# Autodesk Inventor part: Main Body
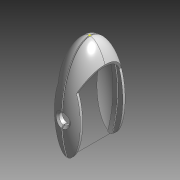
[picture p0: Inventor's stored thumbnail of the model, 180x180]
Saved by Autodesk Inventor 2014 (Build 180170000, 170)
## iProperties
Created: 2013-09
Part Number: Main Body
Material: Generic
Document SubType Name: Modeling
Designer: Joey Mason
Appearance: Reflective - White
Mass: 1001.7 g
Surface Area: 2819.14 cm^2
Volume: 1001.7 cm^3
Density: 1 g/cm^3
Author: Joey Mason
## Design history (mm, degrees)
sketch "Sketch1"
  geometry: L1 (-1045.953, 551.745)-(799.079, 551.745); L2 (799.079, 551.745)-(799.079, -678.891); L3 (799.079, -678.891)-(-1045.953, -678.891); L4 (-1045.953, -678.891)-(-1045.953, 551.745); 4 further points; 1 other entity
  constraints: 1 vertical, 6 other
  node "Image1"
sketch "Sketch6"
  geometry: 5 further points; 1 other entity
  constraints: 1 coincident, 4 other
sketch "Sketch7"
  geometry: 4 further points; 1 other entity
  constraints: 1 coincident, 4 other
sketch "Sketch8"
  geometry: 4 further points; 1 other entity
  constraints: 4 other
sketch "Sketch9"
  geometry: 5 further points; 1 other entity
  constraints: 1 coincident, 2 other
workpoint "Work Point5"
loft "Loft2" dims "d70" = 0, "d71" = 90 deg, "d72" = 0, "d73" = 90 deg, "d74" = 0, "d75" = 90 deg, "d76" = 0, "d77" = 90 deg, "d78" = 0, "d79" = 90 deg, "d80" = 0, "d81" = 90 deg, "d82" = 0, "d83" = 90 deg
workplane "Work Plane1"
sketch "Sketch10"
  geometry: L1 (0, 0)-(0.002, -165.1); L2 (-72.009, 197.105)-(-42.932, 117.215); L3 (-29.628, -144.286)-(-47.688, -246.71); L4 (-47.688, -246.71)-(-267.69, 18.133); L5 (-267.69, 18.133)-(-72.009, 197.105); L6 (267.69, 18.139)-(72.005, 197.107); L7 (72.005, 197.107)-(42.929, 117.216); L8 (47.694, -246.709)-(267.69, 18.139); L9 (29.631, -144.286)-(47.694, -246.709); L10 (-47.688, -246.71)-(-13.839, -360.721); L11 (-13.839, -360.721)-(47.694, -246.709); 3 further points; 2 other entities
  constraints: 22 end point, 5 symmetric about line, 2 coincident, 11 other
extrude "Extrusion1" cut sketch "Sketch10" distance "d91" = 279.4; taper "d92" = 0 deg
sketch "Sketch11"
  geometry: C1 r 25.4 at (0, 0); 1 further point
  constraints: 1 centre point, 1 coincident
  dimensions: "d93" = 50.8 diameter of C1
extrude "Extrusion2" cut sketch "Sketch11" distance "d94" = 27.94; taper "d95" = 0 deg
chamfer "Chamfer1" distance "d96" = 8.89; stored, may be unused: second distance "d97" = 3.175, angle "d98" = 45 deg
sketch "Sketch12"
  geometry: L1 (0, 0)-(0, -167.37); L2 (0, -167.37)-(2.54, -167.37); L3 (2.54, -167.37)-(-2.54, -167.37); L4 (-2.54, -167.37)-(2.54, -167.37); L5 (2.54, -167.37)-(2.54, 281.907); L6 (2.54, 281.907)-(-2.54, 281.907); L7 (-2.54, 281.907)-(-2.54, -167.37)
  constraints: 14 end point, 2 parallel, 2 perpendicular, 1 collinear, 1 horizontal, 1 vertical
  dimensions: "d99" = 2.54 distance of L1.end L2.end; "d100" = 5.08 distance of L2.end L3.end
extrude "Extrusion3" cut sketch "Sketch12" distance "d101" = 279.4; taper "d102" = 0 deg
sketch "Sketch13"
  geometry: L1 (-226.06, 132.496)-(-244.523, 132.496) reference; L2 (-226.06, 81.95)-(-226.06, 132.496) reference; L3 (-15.372, -57.733)-(-228.468, -57.733) reference; L4 (-121.92, 107.223)-(-121.92, 381.543); L5 (-121.92, 107.223)-(5.08, 107.223); L6 (-223.393, -57.733)-(-20.447, -57.733); L7 (-226.06, 132.496)-(-226.06, 133.766); L8 (-247.93, 141.407)-(-240.289, 133.766); L9 (-240.289, 133.766)-(-226.06, 133.766); L10 (-226.06, 132.496)-(-226.06, 81.95); L11 (-247.93, 73.04)-(-240.289, 80.68); L12 (-226.06, 81.95)-(-226.06, 80.68); L13 (-226.06, 80.68)-(-240.289, 80.68); 1 further point; 2 other entities
  constraints: 20 end point, 3 perpendicular, 2 horizontal, 2 point on line, 1 coincident, 1 collinear, 1 parallel, 8 other
  dimensions: "d103" = 274.32 distance of L4.start L4.end; "d104" = 127 distance of L4.start L5.end; "d106" = 1.27 distance of L1.start L7.end
extrude "Extrusion4" join sketch "Sketch13" distance "d108" = 5.08; taper "d109" = 0 deg
shell "Shell1" dims "d110" = 7.62
body "Solid2"
other parameters: "d85" = 132.08
